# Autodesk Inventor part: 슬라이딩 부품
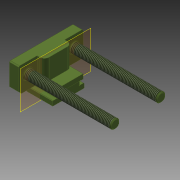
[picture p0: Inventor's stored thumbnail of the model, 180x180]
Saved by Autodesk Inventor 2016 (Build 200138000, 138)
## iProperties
Created: 2017-04
Part Number: 슬라이딩 부품
Material: 강철, 연강
Document SubType Name: Modeling
Designer: mduedu
Density: 7.86 g/cm^3
Appearance: 올리브 녹색
Mass: 390.322 g
Surface Area: 152.125 cm^2
Volume: 49.6593 cm^3
Author: mduedu
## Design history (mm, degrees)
sketch "스케치1"
  geometry: L1 (37, 35)-(10, 35); L2 (0, 17)-(0, 0); L3 (0, 17)-(5, 17); L4 (5, 17)-(5, 12); L5 (5, 12)-(10, 12); L6 (10, 12)-(10, 35); L7 (37, 35)-(37, 0); L8 (37, 0)-(0, 0); L9 (37, -35)-(10, -35); L10 (0, -17)-(0, 0); L11 (0, -17)-(5, -17); L12 (5, -17)-(5, -12); L13 (5, -12)-(10, -12); L14 (10, -12)-(10, -35); L15 (37, -35)-(37, 0)
  constraints: 30 end point, 6 symmetric about line, 3 perpendicular, 2 horizontal, 2 point on line, 2 vertical
  dimensions: "d39" = 5 distance of L2.start L3.end; "d41" = 70 distance between parallel lines of L9 L1; "d42" = 27 distance of L9.start L9.end; "d43" = 24 distance between parallel lines of L13 L5; "d44" = 5 distance of L4.end L5.end; "d45" = 34 distance between parallel lines of L11 L3
extrude "돌출1" new body sketch "스케치1" distance "d5" = 10; taper "d6" = 0 deg
sketch "스케치2"
  geometry: L1 (-35, 10)-(-35, 37) reference; L2 (17, 0)-(-17, 0) reference; L3 (-17, 0)-(-17, 5) reference; L4 (-17, 5)-(-12, 5) reference; L5 (-12, 5)-(-12, 10) reference; L6 (-12, 10)-(-35, 10) reference; L7 (-35, 37)-(35, 37) reference; L8 (35, 37)-(35, 10) reference; L9 (35, 10)-(12, 10) reference; L10 (12, 10)-(12, 5) reference; L11 (12, 5)-(17, 5) reference; L12 (17, 5)-(17, 0) reference; L13 (-12, 10)-(-15, 10); L14 (-15, 10)-(-15, 15); L15 (-15, 15)-(15, 15); L16 (15, 15)-(15, 10); L17 (15, 10)-(12, 10)
  constraints: 10 end point, 4 perpendicular, 2 point on line
  dimensions: "d46" = 3 distance between parallel lines of L14 L5; "d47" = 3 distance between parallel lines of L16 L10 (= d46); "d48" = 5 distance of L13.end L14.end
extrude "돌출2" join sketch "스케치2" distance "d12" = 20; taper "d13" = 0 deg
sketch "스케치3"
  geometry: L1 (0, 20)-(8, 20); L2 (8, 20)-(8, 50); L3 (8, 50)-(0, 50); L4 (0, 50)-(0, 20); L5 (0, 50)-(20, 50) reference; L6 (0, 20)-(20, 20) reference; L7 (0, 0)-(0, 70) reference; 2 further points
  constraints: 8 end point, 2 midpoint, 2 parallel, 1 horizontal, 1 perpendicular, 1 point on line
  dimensions: "d14" = 8 distance between parallel lines of L2 L4
extrude "돌출3" join sketch "스케치3" stored distance "d16" = 20; taper "d17" = 0 deg
fillet "모깎기1" dims "d18" = 5
sketch "스케치4"
  geometry: L1 (-15, 10)-(-35, 10) reference; L2 (-35, 10)-(-35, 37) reference; C1 r 5 at (-25, 25); 1 further point
  constraints: 1 centre point
  dimensions: "d19" = 10 diameter of C1; "d23" = 25 horizontal distance of point (0, 0) C1.centre (derived); "d49" = 15 distance from line of C1.centre L1; "d50" = 10 distance from line of C1.centre L2
extrude "돌출4" join sketch "스케치4" distance "d24" = 95; taper "d25" = 0 deg
feature "스레드1" dims "d26" = 10, "d27" = 0
chamfer "모따기1" distance "d28" = 1; stored, may be unused: second distance "d29" = 2, angle "d30" = 45 deg
fillet "모깎기2" dims "d31" = 1
sketch "스케치5"
  geometry: L1 (-12, 5)-(-12, 10) reference; L2 (12, 10)-(12, 5) reference; C1 r 0.5 at (-12, 10); C2 r 0.5 at (-12, 5); C3 r 0.5 at (12, 5); C4 r 0.5 at (12, 10); 1 further point
  constraints: 4 centre point, 4 coincident, 3 equal radius
  dimensions: "d51" = 1 diameter of C1
extrude "돌출5" cut sketch "스케치5" stored distance "d34" = 89; taper "d35" = 0 deg
chamfer "모따기2" distance "d36" = 3; stored, may be unused: second distance "d37" = 2, angle "d38" = 45 deg
chamfer "모따기3" distance "d52" = 0.5; stored, may be unused: second distance "d53" = 2, angle "d54" = 45 deg
sketch "스케치6"
  geometry: L1 (16.5, 5)-(17, 4.5) reference; L2 (16.5, 5)-(12.5, 5) reference; L3 (12, 5.5)-(12, 9.5) reference; L4 (-32, 10)-(-12.5, 10) reference; L5 (-12, 9.5)-(-12, 5.5) reference; L6 (-12.5, 5)-(-16.5, 5) reference; L7 (-17, 4.5)-(-16.5, 5) reference; L8 (-17, 4.5)-(-17, 0) reference; L9 (-17, 0)-(17, 0) reference; L10 (17, 0)-(17, 4.5) reference; L11 (11.5, 10)-(-11.5, 10); L12 (16.5, 5)-(17, 4.5) reference; L13 (16.5, 5)-(12.5, 5) reference; L14 (12, 5.5)-(12, 9.5) reference; L15 (12.5, 10)-(32, 10) reference; L16 (35, 13)-(32, 10) reference; L17 (35, 13)-(35, 36) reference; L18 (34, 37)-(-34, 37) reference; L19 (-35, 36)-(-35, 13) reference; L20 (-32, 10)-(-35, 13) reference; L21 (-32, 10)-(-12.5, 10) reference; L22 (-12, 9.5)-(-12, 5.5) reference; L23 (-12.5, 5)-(-16.5, 5) reference; L24 (-17, 4.5)-(-16.5, 5) reference; L25 (-17, 4.5)-(-17, 0) reference; L26 (-17, 0)-(17, 0) reference; L27 (17, 0)-(17, 4.5) reference; L28 (11.5, 5)-(-11.5, 5); L29 (34, 37)-(35, 36) reference; L30 (-35, 36)-(-34, 37) reference; A1 r 0.5 centre (12, 5) between (12, 5.5) and (12.5, 5) reference; A2 r 0.5 centre (12, 10) between (12.5, 10) and (12, 9.5) reference; A3 r 0.5 centre (-12, 10) between (-12, 9.5) and (-12.5, 10) reference; A4 r 0.5 centre (-12, 5) between (-12.5, 5) and (-12, 5.5) reference; A5 r 0.5 centre (12, 5) between (12, 5.5) and (12.5, 5) reference; A6 r 0.5 centre (12, 10) between (12.5, 10) and (12, 9.5) reference; A7 r 0.5 centre (-12, 10) between (-12, 9.5) and (-12.5, 10) reference; A8 r 0.5 centre (-12, 5) between (-12.5, 5) and (-12, 5.5) reference; 1 further point
  constraints: 4 end point, 4 point on circle, 2 collinear, 2 perpendicular
extrude "돌출6" cut sketch "스케치6" distance "d55" = 1; taper "d56" = 0 deg
node "작업 평면1"
sketch "스케치7"
  geometry: C1 r 4.2 at (-23, 25.5) reference; C2 r 4.2 at (23, 25.5) reference; 3 further points
  constraints: 2 coincident
hole "구멍1" sketch "스케치7" at (-23, 25.5), (23, 25.5) diameter "d57" = 3.242; stored, may be unused: countersink angle "d61" = 90 deg, drill point angle "d63" = 118 deg; dims "d58" = 6, "d59" = 4, "d60" = 2, "d62" = 8
mirror "대칭2"
mirror "대칭3"
node "솔리드2"
node "투영된 루프1"
node "투영된 루프2"
node "참조1"
node "참조2"
node "솔리드1"
